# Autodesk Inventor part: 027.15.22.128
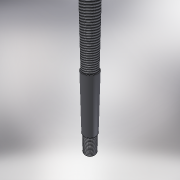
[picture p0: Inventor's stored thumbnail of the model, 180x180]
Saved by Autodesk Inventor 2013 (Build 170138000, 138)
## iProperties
Shininess: 64.0
Length Units: 11269
Angle Units: 11279
Time Units: 11290
Mass Units: 11283
Length Display Precision: 3
Angle Display Precision: 2
Created: 2002-02
Part Number: 027.15.22.128
Material: Steel, Mild
Document SubType Name: Modeling
Designer: SOleg
Density: 7.86 g/cm^3
Density: 0.0
Volumn: 0.0
Area: 0.0
PropertySet Name: Model Information
Control State: 0
Master: False
Checked Out: True
Author: SOleg
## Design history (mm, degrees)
sketch "Sketch1"
  geometry: C1 r 10 at (0, 0)
  constraints: 1 centre point
  dimensions: "d0" = 20 diameter of C1
extrude "Extrusion1" new body sketch "Sketch1" distance "d1" = 75; taper "d2" = 0 deg
sketch "Sketch2"
  geometry: C1 r 10 at (0, 0) reference; C2 r 11 at (0, 0)
  constraints: 1 centre point, 1 coincident
  dimensions: "d5" = 22 diameter of C2
extrude "Extrusion2" join sketch "Sketch2" distance "d3" = 90; taper "d4" = 0 deg
sketch "Sketch3"
  geometry: C1 r 11 at (0, 0) reference; C2 r 10 at (0, 0)
  constraints: 1 centre point, 1 coincident
  dimensions: "d6" = 20 diameter of C2
extrude "Extrusion3" join sketch "Sketch3" distance "d7" = 36; taper "d8" = 0 deg
thread "Thread1" dims "d9" = 10, "d10" = 0
thread "Thread2" dims "d11" = 10, "d12" = 0
body "Solid1"
